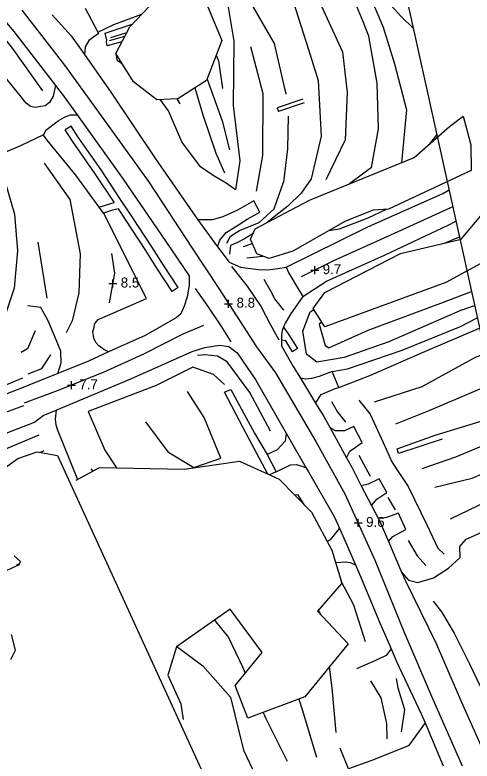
# Model space of a CAD drawing. Extents: x 2316231 to 2323598, y 363169 to 371906.
# Drawn here: x 2320809.7 to 2321039.3, y 364491.7 to 364866.8 of the extents above; entities that cross this region are included whole.
import ezdxf

# ---------------------------------------------------------------- set-up
doc = ezdxf.new("R2010")
doc.units = 0
for name, color, linetype in [('RD_DTM_BkLn1', 7, 'Continuous'), ('RD_DTM_BkLn2', 7, 'Continuous'), ('RD_DTM_Holes', 7, 'Continuous'), ('RD_DTM_TinHull', 7, 'Continuous'), ('RD_DTM_Void', 7, 'Continuous'), ('RD_EX_Road', 7, 'Continuous')]:
    doc.layers.add(name, color=color, linetype=linetype)

msp = doc.modelspace()

# ---------------------------------------------------------------- linework, layer by layer
at = {"layer": 'RD_DTM_BkLn1'}
for p, q in [((2320857.922, 364855.442), (2320865.884, 364857.984)), ((2320857.161, 364854.013), (2320864.941, 364856.17)), ((2320890.993, 364824.643), (2320892.539, 364822.049)), ((2321021.612, 364806.726), (2321017.953, 364801.935)), ((2320988.788, 364790.183), (2320977.746, 364781.912)), ((2320825.894, 364724.379), (2320821.285, 364752.599)), ((2321025.529, 364752.138), (2321033.007, 364755.165)), ((2320924.511, 364750.44), (2320928.932, 364751.87)), ((2320926.195, 364744.639), (2320934.141, 364745.607)), ((2321034.418, 364718.599), (2321040.607, 364720.781)), ((2321020.775, 364655.454), (2321052.876, 364665.268)), ((2320821.672, 364655.549), (2320782.321, 364639.059)), ((2320822.25, 364646.821), (2320824.303, 364647.793)), ((2320982.482, 364645.549), (2320988.198, 364634.922)), ((2320847.881, 364638.589), (2320848.738, 364637.393)), ((2320997.044, 364624.211), (2321000.661, 364617.915)), ((2320962.235, 364567.615), (2320963.132, 364565.607))]:
    msp.add_line(p, q, dxfattribs=at)
for points in [[(2320908.522, 364997.717), (2320917.208, 364986.663), (2320929.547, 364969.312), (2320941.727, 364952.475), (2320951.651, 364938.282), (2320962.989, 364924.745), (2320974.367, 364912.172), (2320983.382, 364900.815), (2320991.979, 364890.119), (2320998.704, 364879.261), (2320998.587, 364871.774), (2321003.76, 364866.025), (2321009.84, 364859.987)], [(2320789.301, 364937.875), (2320795.11, 364943.095), (2320806.689, 364952.583), (2320818.553, 364960.506), (2320831.082, 364969.075), (2320846.132, 364977.365), (2320860.519, 364984.44), (2320870.598, 364987.867), (2320889.653, 364988.831), (2320900.365, 364987.807), (2320908.475, 364980.988), (2320916.282, 364973.127), (2320926.017, 364960.544), (2320937.809, 364940.963), (2320942.748, 364927.859), (2320950.518, 364916.033), (2320963.998, 364909.262), (2320972.13, 364900.847), (2320985.96, 364881.366), (2320994.687, 364860.701), (2321000.435, 364842.191), (2321006.362, 364819.106), (2321003.87, 364792.554)], [(2320810.535, 364940.389), (2320825.111, 364948.104), (2320854.856, 364964.167), (2320876.979, 364971.002), (2320892.242, 364970.12), (2320908.18, 364962.846), (2320915.576, 364953.824), (2320929.031, 364935.515), (2320932.634, 364927.541), (2320935.334, 364914.389), (2320942.929, 364902.839), (2320955.2, 364890.276), (2320964.566, 364869.376), (2320974.238, 364848.22), (2320976.597, 364827.739), (2320975.536, 364803.965), (2320965.865, 364783.98)], [(2320842.068, 364950.483), (2320865.195, 364952.17), (2320885.293, 364946.76), (2320899.752, 364933.281), (2320911.245, 364920.421), (2320921.248, 364895.307), (2320929.317, 364870.652), (2320939.891, 364852.388), (2320945.723, 364827.042)], [(2320810.699, 364934.838), (2320827.79, 364939.679), (2320849.336, 364941.617), (2320871.046, 364940.278), (2320885.78, 364932.975), (2320899.408, 364919.593), (2320903.204, 364911.842), (2320908.706, 364897.372), (2320916.477, 364872.722), (2320919.668, 364853.585), (2320919.271, 364821.299), (2320922.598, 364793.419), (2320920.431, 364778.915), (2320915.816, 364782.273), (2320909.315, 364786.101), (2320902.858, 364790.501), (2320893.539, 364802.97), (2320886.757, 364818.567), (2320882.826, 364824.202)], [(2320988.788, 364790.183), (2320992.4, 364809.56), (2320991.664, 364832.54), (2320987.459, 364856.087), (2320984.732, 364862.94), (2320979.791, 364875.211), (2320973.159, 364886.674), (2320968.431, 364894.237), (2320960.28, 364902.211), (2320953.763, 364908.088)], [(2320776.661, 364884.847), (2320788.473, 364874.922), (2320808.365, 364850.154), (2320823.472, 364828.593)], [(2320941.949, 364883.529), (2320949.496, 364873.493), (2320957.099, 364849.476), (2320961.964, 364833.885), (2320963.6, 364805.937), (2320958.573, 364784.428), (2320953.495, 364777.255), (2320946.856, 364770.739), (2320940.697, 364765.929), (2320936.198, 364762.314)], [(2320813.139, 364869.191), (2320834.594, 364841.589), (2320851.668, 364817.936), (2320876.795, 364782.989), (2320898.779, 364749.615), (2320912.035, 364729.273), (2320922.885, 364712.636), (2320930.999, 364700.019), (2320940.535, 364686.939), (2320960.87, 364652.4), (2320975.496, 364625.988), (2320990.714, 364592.422), (2321005.138, 364556.892), (2321019.52, 364523.148), (2321034.445, 364489.194)], [(2320931.017, 364778.19), (2320934.191, 364796.18), (2320934.318, 364827.196), (2320928.233, 364850.784)], [(2320863.597, 364842.267), (2320861.179, 364843.674), (2320860.575, 364847.214)], [(2320910.841, 364846.594), (2320912.012, 364843.738), (2320913.974, 364829.788)], [(2320906.209, 364834.493), (2320913.805, 364813.62), (2320917.411, 364799.049)], [(2320900.135, 364830.126), (2320904.026, 364816.524), (2320910.633, 364797.345), (2320915.015, 364787.429)], [(2320946.966, 364815.913), (2320946.685, 364799.414), (2320944.555, 364782.729)], [(2320824.405, 364792.273), (2320837.253, 364773.974), (2320842.399, 364746.638), (2320841.726, 364727.144), (2320838.397, 364713.014), (2320835.41, 364707.024)], [(2320804.969, 364782.158), (2320809.477, 364766.572), (2320810.929, 364748.236), (2320809.327, 364729.495), (2320804.968, 364716.442)], [(2320916.177, 364752.035), (2320918.054, 364755.578), (2320922.54, 364758.389), (2320932.344, 364762.499), (2320939.963, 364769.286), (2320944.555, 364782.729)], [(2321029.649, 364770.36), (2321028.562, 364769.832), (2320998.376, 364756.039), (2320969.418, 364743.083), (2320953.527, 364735.056)], [(2320967.442, 364758.383), (2320972.671, 364759.298), (2320987.129, 364764.799), (2320996.273, 364769.142)], [(2320929.338, 364756.954), (2320924.927, 364754.161), (2320921.553, 364752.368), (2320917.909, 364750.865), (2320917.401, 364746.538)], [(2320858.168, 364746.844), (2320859.763, 364736.924), (2320857.077, 364722.011)], [(2320918.448, 364740.354), (2320926.378, 364730.455), (2320933.383, 364719.986), (2320937.916, 364711.366), (2320942.307, 364703.534)], [(2320944.73, 364718.404), (2320940.305, 364724.022), (2320938.162, 364727.865), (2320934.943, 364733.75)], [(2320900.307, 364729.302), (2320906.595, 364720.214), (2320913.076, 364710.503), (2320918.189, 364702.434)], [(2320963.869, 364712.319), (2320962.491, 364711.256), (2320965.515, 364700.528), (2320967.366, 364699.38), (2320987.153, 364708.335), (2321023.587, 364721.971), (2321039.079, 364727.692)], [(2321034.418, 364718.599), (2320997.539, 364702.41), (2320975.149, 364694.543), (2320961.373, 364692.27), (2320956.232, 364696.255), (2320954.387, 364707.739), (2320957.933, 364717.495), (2320959.882, 364718.675)], [(2320904.423, 364710.71), (2320894.102, 364706.322), (2320873.866, 364696.029), (2320854.031, 364687.027), (2320830.834, 364677.768), (2320814.306, 364671.594)], [(2320819.876, 364708.052), (2320815.948, 364698.981), (2320812.768, 364697.043)], [(2320816.327, 364686.282), (2320823.14, 364689.081), (2320827.664, 364695.905)], [(2320938.122, 364657.459), (2320927.699, 364676.97), (2320916.269, 364692.319), (2320911.385, 364695.205), (2320905.037, 364695.876), (2320901.375, 364695.504)], [(2320990.259, 364672.362), (2321014.229, 364680.025), (2321041.059, 364694.717), (2321045.94, 364696.648)], [(2320914.937, 364680.992), (2320909.408, 364686.067), (2320898.975, 364689.695), (2320880.565, 364680.504), (2320846.533, 364667.426)], [(2320813.41, 364684.179), (2320805.414, 364680.785), (2320801.821, 364679.874), (2320798.958, 364679.173), (2320796.598, 364678.011), (2320792.846, 364676.308), (2320784.749, 364672.755)], [(2321000.981, 364661.288), (2321017.755, 364667.968), (2321049.323, 364681.342)], [(2320875.266, 364662.179), (2320886.462, 364647.072), (2320899.545, 364639.283), (2320913.06, 364643.883), (2320904.689, 364664.446), (2320896.331, 364677.496)], [(2320982.52, 364673.174), (2320988.09, 364666.157), (2320994.714, 364651.896), (2320999.151, 364641.717), (2321007.276, 364629.755), (2321016.756, 364610.067), (2321022.174, 364598.635), (2321025.367, 364595.667)], [(2320761.146, 364648.891), (2320785.759, 364659.479), (2320805.172, 364667.165), (2320814.1, 364670.455)], [(2320968.792, 364672.459), (2320971.631, 364667.461), (2320975.773, 364662.027)], [(2320846.533, 364667.426), (2320854.791, 364648.019), (2320860.746, 364639.052)], [(2321014.287, 364638.778), (2321031.215, 364644.622), (2321055.222, 364654.654)], [(2321020.583, 364629.392), (2321039.348, 364633.933), (2321058.029, 364641.952)], [(2320950.129, 364625.49), (2320951.583, 364625.742), (2320954.793, 364620.717)], [(2321028.55, 364613.491), (2321047.002, 364622.383), (2321061.146, 364627.85)], [(2321007.232, 364602.535), (2321011.839, 364594.855), (2321016.049, 364589.955)], [(2320810.975, 364589.985), (2320810.794, 364590.419), (2320812.056, 364590.993)], [(2320973.443, 364582.365), (2320979.842, 364570.277), (2320985.637, 364551.755)], [(2321019.82, 364572.13), (2321023.963, 364566.779), (2321030.308, 364555.987), (2321038.093, 364540.576), (2321049.079, 364517.388), (2321059.888, 364492.083)], [(2320909.879, 364562.492), (2320916.976, 364553.731), (2320923.95, 364539.036), (2320925.409, 364535.836)], [(2320891.035, 364549.213), (2320904.038, 364539.597), (2320917.997, 364523.792), (2320924.509, 364497.066), (2320931.829, 364481.592)], [(2320967.573, 364539.046), (2320968.95, 364528.522), (2320970.956, 364506.022)], [(2320988.39, 364532.029), (2320993.458, 364523.389), (2320996.33, 364510.532), (2320996.484, 364502.885)], [(2321001.28, 364533.233), (2321002.05, 364528.41), (2321005.381, 364517.535), (2321003.705, 364506.285)], [(2320952.287, 364522.819), (2320954.039, 364517.633), (2320961.129, 364493.542)], [(2320934.422, 364516.063), (2320935.785, 364513.072), (2320946.394, 364491.688)]]:
    msp.add_lwpolyline(points, dxfattribs=at)
at = {"layer": 'RD_DTM_BkLn2'}
for points in [[(2320813.835, 364679.431), (2320798.583, 364673.706), (2320785.827, 364668.854), (2320775.48, 364664.655), (2320768.989, 364662.198), (2320754.788, 364656.259), (2320754.267, 364655.838), (2320754.259, 364655.36)], [(2320776.858, 364644.163), (2320782.736, 364647.15), (2320793.891, 364652.025), (2320806.074, 364656.853), (2320819.585, 364662.004)]]:
    msp.add_lwpolyline(points, dxfattribs=at)
at = {"layer": 'RD_DTM_Holes'}
for points in [[(2320860.417, 364847.473), (2320867.353, 364860.808), (2320880.49, 364874.76), (2320895.367, 364877.398), (2320906.613, 364870.852), (2320913.685, 364854.024), (2320905.951, 364833.819), (2320891.544, 364824.673), (2320880.937, 364824.1), (2320869.171, 364833.142), (2320860.417, 364847.473)], [(2321034.819, 364815.97), (2321038.641, 364801.467), (2321038.928, 364788.615), (2320997.295, 364769.213), (2320989.643, 364768.678), (2320975.695, 364763.049), (2320949.218, 364748.078), (2320937.431, 364744.392), (2320931.133, 364746.717), (2320928.02, 364754.005), (2320930.34, 364759.196), (2320957.595, 364773.703), (2321010.179, 364795.124), (2321027.925, 364810.672), (2321034.819, 364815.97)], [(2321043.787, 364765.784), (2321045.794, 364751.691), (2321043.724, 364741.876), (2321026.13, 364732.303), (2320965.317, 364710.009), (2320959.555, 364719.196), (2320965.397, 364727.297), (2321003.341, 364746.852), (2321033.829, 364754.116), (2321043.787, 364765.784)], [(2320791.882, 364630.089), (2320811.181, 364643.862), (2320820.79, 364647.063), (2320831.038, 364645.366), (2320909.676, 364473.622)], [(2320840.465, 364632.876), (2320852.094, 364639.226), (2320894.708, 364638.37), (2320922.515, 364642.378), (2320942.367, 364633.435), (2320958.623, 364616.797), (2320968.805, 364597.777), (2320973.842, 364581.04), (2320961.764, 364567.071), (2320977.071, 364550.686), (2320955.245, 364523.937), (2320926.761, 364513.165), (2320920.338, 364529.614), (2320933.898, 364546.251), (2320917.807, 364568.078), (2320890.778, 364549.032), (2320886.556, 364534.904), (2320893.105, 364520.406), (2320894.155, 364512.555)], [(2320802.932, 364586.35), (2320810.468, 364589.756), (2320811.853, 364590.382), (2320812.411, 364592.061), (2320809.356, 364594.862)], [(2320807.609, 364542.745), (2320809.884, 364547.472), (2320807.907, 364555.292)]]:
    msp.add_lwpolyline(points, dxfattribs=at)
at = {"layer": 'RD_DTM_TinHull'}
msp.add_lwpolyline([(2320809.363, 365353.877), (2320991.706, 364942.038), (2321080.196, 364541.654), (2321314.653, 364017.924), (2320828.919, 363723.372), (2320765.1, 363867.546), (2320638.089, 364094.01), (2320532.322, 364258.493), (2320402.792, 364459.125), (2320263.728, 364603.235), (2320177.718, 364755.167), (2319998.644, 364909.111), (2319975.332, 365147.552), (2319890.016, 365354.444)], dxfattribs=at)
at = {"layer": 'RD_DTM_Void'}
for p, q in [((2320958.3, 364738.477), (2320962.3, 364738.477)), ((2320960.3, 364736.477), (2320960.3, 364740.477)), ((2320858.834, 364729.764), (2320858.834, 364733.764)), ((2320856.834, 364731.764), (2320860.834, 364731.764)), ((2320917.02, 364719.63), (2320917.02, 364723.63)), ((2320915.02, 364721.63), (2320919.02, 364721.63)), ((2320836.03, 364680.64), (2320840.03, 364680.64)), ((2320838.03, 364678.64), (2320838.03, 364682.64)), ((2320982.114, 364609.39), (2320982.114, 364613.39)), ((2320980.114, 364611.39), (2320984.114, 364611.39))]:
    msp.add_line(p, q, dxfattribs=at)
at = {"layer": 'RD_EX_Road'}
for p, q in [((2320845.019, 364870.149), (2320851.364, 364858.212)), ((2320830.127, 364831.326), (2320832.3, 364828.51)), ((2320954.342, 364824.406), (2320941.474, 364820.046)), ((2320941.474, 364820.046), (2320942.081, 364818.252)), ((2320954.95, 364822.612), (2320942.081, 364818.252)), ((2320837.948, 364810.904), (2320834.943, 364808.964)), ((2320854.239, 364767.074), (2320852.033, 364770.099)), ((2320901.513, 364763.876), (2320911.477, 364750.268)), ((2320891.659, 364729.693), (2320888.671, 364727.727)), ((2320972.379, 364679.559), (2320969.028, 364687.59)), ((2320953.082, 364684.116), (2320960.744, 364671.653)), ((2320968.037, 364659.164), (2320976.267, 364644.152)), ((2320946.018, 364656.484), (2320955.902, 364639.311)), ((2320936.38, 364645.769), (2320940.852, 364637.066)), ((2320940.852, 364637.066), (2320937.557, 364635.602)), ((2320983.678, 364630.11), (2320988.848, 364620.091)), ((2320988.848, 364620.091), (2320992.106, 364613.776)), ((2320972.674, 364608.72), (2320980.76, 364590.26)), ((2320997.326, 364602.026), (2321003.903, 364586.719)), ((2321015.798, 364510.839), (2321024.89, 364489.308))]:
    msp.add_line(p, q, dxfattribs=at)
for points in [[(2320830.127, 364831.326), (2320828.955, 364825.935), (2320826.977, 364822.775), (2320824.855, 364821.093), (2320822.706, 364820.71), (2320820.21, 364820.261), (2320817.564, 364820.826), (2320815.279, 364822.469), (2320812.068, 364826.508), (2320797.38, 364844.432), (2320771.545, 364875.949), (2320769.061, 364876.249), (2320765.48, 364877.96), (2320763.665, 364879.93), (2320762.196, 364882.667), (2320762.258, 364885.893), (2320764.822, 364889.164), (2320769.089, 364891.002), (2320775.022, 364892.731), (2320777.755, 364893.117), (2320780.488, 364892.295)], [(2320780.488, 364892.295), (2320781.839, 364890.827), (2320809.138, 364858.525), (2320830.127, 364831.326)], [(2320828.446, 364866.907), (2320837.849, 364856.386), (2320844.587, 364846.845)], [(2320851.364, 364858.212), (2320859.321, 364861.945), (2320873.393, 364867.223)], [(2320863.458, 364853.319), (2320855.951, 364851.222), (2320855.616, 364853.43), (2320855.914, 364854.187), (2320855.038, 364857.582), (2320868.61, 364862.142)], [(2320851.364, 364858.212), (2320851.715, 364857.551), (2320846.73, 364853.985), (2320844.966, 364850.845), (2320844.587, 364846.845)], [(2320844.587, 364846.845), (2320857.898, 364827.996), (2320880.008, 364795.049), (2320900.36, 364765.451), (2320901.513, 364763.876)], [(2320832.3, 364828.51), (2320833.636, 364826.779), (2320840.874, 364816.632)], [(2320824.14, 364806.552), (2320825.116, 364808.837), (2320831.477, 364813.584), (2320834.89, 364815.543), (2320837.514, 364816.645), (2320840.874, 364816.632)], [(2320840.874, 364816.632), (2320863.967, 364784.261), (2320885.411, 364752.92), (2320897.166, 364735.566), (2320897.131, 364731.018), (2320896.288, 364725.078), (2320894.726, 364720.327), (2320892.976, 364716.544), (2320890.633, 364714.45), (2320875.088, 364705.702), (2320856.744, 364697.372)], [(2320852.033, 364770.099), (2320857.774, 364772.067), (2320859.551, 364772.491), (2320859.477, 364772.602), (2320849.993, 364786.881), (2320838.516, 364803.43), (2320834.943, 364808.964)], [(2320891.659, 364729.693), (2320884.236, 364740.975), (2320878.395, 364750.254), (2320868.243, 364765.875), (2320862.456, 364774.581), (2320852.953, 364788.89), (2320841.489, 364805.42), (2320837.948, 364810.904)], [(2320824.044, 364806.52), (2320812.54, 364801.043), (2320800.842, 364796.154), (2320784.183, 364785.435)], [(2320852.033, 364770.099), (2320840.232, 364786.287), (2320825.824, 364803.849), (2320824.09, 364806.436), (2320824.14, 364806.552)], [(2320945.959, 364739.913), (2320959.185, 364746.589), (2320986.591, 364760.069), (2321024.734, 364777.108), (2321027.781, 364778.81)], [(2320911.477, 364750.268), (2320912.664, 364753.542), (2320915.856, 364757.386), (2320922.036, 364761.207), (2320926.32, 364764.093), (2320932.674, 364767.614), (2320929.643, 364773.341), (2320921.485, 364768.646), (2320914.194, 364765.354), (2320908.694, 364763.857), (2320901.513, 364763.876)], [(2320856.744, 364697.372), (2320854.367, 364698.679), (2320851.883, 364700.504), (2320850.396, 364702.087), (2320849.288, 364704.355), (2320848.78, 364707.661), (2320849.257, 364709.237), (2320849.879, 364711.704), (2320851.566, 364713.726), (2320856.158, 364715.726), (2320875.7, 364724.304), (2320862.202, 364751.294), (2320854.466, 364766.763), (2320854.239, 364767.074)], [(2320888.671, 364727.727), (2320881.229, 364739.039), (2320875.382, 364748.327), (2320865.254, 364763.91), (2320861.66, 364769.317), (2320858.771, 364768.628), (2320854.239, 364767.074)], [(2320954.385, 364725.183), (2320966.129, 364733.025), (2320995.422, 364746.083), (2321027.27, 364761.065), (2321031.261, 364763.065)], [(2320911.477, 364750.268), (2320912.566, 364748.781), (2320917.308, 364742.497)], [(2320917.308, 364742.497), (2320922.955, 364739.986), (2320933.163, 364738.672), (2320938.154, 364738.808), (2320941.771, 364739.395), (2320945.959, 364739.913)], [(2320945.959, 364739.913), (2320947.271, 364737.035), (2320951.507, 364729.955), (2320954.385, 364725.183)], [(2320954.385, 364725.183), (2320948.198, 364716.325), (2320945.436, 364711.784), (2320944.632, 364709.812)], [(2320831.261, 364686.537), (2320832.982, 364691.833), (2320832.717, 364697.731), (2320830.389, 364703.423), (2320826.324, 364713.048), (2320822.629, 364719.691), (2320815.975, 364720.568)], [(2320969.028, 364687.59), (2320976.704, 364688.887), (2321004.155, 364698.329), (2321033.596, 364710.17), (2321041.984, 364714.549)], [(2320944.632, 364709.812), (2320947.214, 364705.898), (2320951.644, 364699.113), (2320949.153, 364697.39), (2320945.704, 364703.016), (2320943.672, 364703.23)], [(2320944.632, 364709.812), (2320943.975, 364708.199), (2320943.68, 364706.049), (2320943.672, 364703.23)], [(2320972.379, 364679.559), (2320987.927, 364685.461), (2321017.132, 364698.198), (2321043.125, 364709.385)], [(2320943.672, 364703.23), (2320943.664, 364700.464), (2320949.396, 364690.111), (2320953.082, 364684.116)], [(2320830.392, 364668.158), (2320867.973, 364683.892), (2320898.656, 364697.523), (2320905.024, 364699.65), (2320912.507, 364700.724), (2320917.165, 364700.104), (2320921.293, 364696.86), (2320930.677, 364683.175), (2320943.463, 364660.924), (2320946.018, 364656.484)], [(2320856.744, 364697.372), (2320846.619, 364692.775), (2320831.261, 364686.537)], [(2320831.261, 364686.537), (2320816.637, 364680.597), (2320813.84, 364679.529)], [(2320969.028, 364687.59), (2320962.474, 364684.989), (2320958.637, 364684.072), (2320955.654, 364683.643), (2320953.082, 364684.116)], [(2320936.81, 364635.938), (2320924.372, 364659.162), (2320914.936, 364677.074), (2320918.125, 364678.489), (2320930.035, 364656.549), (2320936.38, 364645.769)], [(2320960.744, 364671.653), (2320963.535, 364675.911), (2320970.538, 364679.052), (2320972.379, 364679.559)], [(2320960.744, 364671.653), (2320964.852, 364664.971), (2320968.037, 364659.164)], [(2320819.585, 364662.004), (2320823.83, 364665.41), (2320830.392, 364668.158)], [(2320830.392, 364668.158), (2320829.957, 364663.576), (2320830.295, 364660.785), (2320830.856, 364658.561), (2320841.027, 364633.183)], [(2320976.267, 364644.152), (2320977.867, 364647.42), (2320984.129, 364651.918), (2320980.001, 364659.805), (2320975.218, 364657.725), (2320970.753, 364657.783), (2320968.037, 364659.164)], [(2320946.018, 364656.484), (2320945.465, 364652.581), (2320941.502, 364648.142), (2320936.38, 364645.769)], [(2321024.401, 364653.54), (2321002.461, 364646.274), (2321001.702, 364648.726), (2321020.775, 364655.454)], [(2320976.267, 364644.152), (2320979.081, 364639.018), (2320983.678, 364630.11)], [(2320940.852, 364637.066), (2320948.089, 364640.669), (2320951.198, 364640.751), (2320955.902, 364639.311)], [(2320955.902, 364639.311), (2320957.224, 364637.013), (2320970.08, 364614.641), (2320972.674, 364608.72)], [(2320988.848, 364620.091), (2320991.494, 364623.357), (2320996.465, 364626.756), (2320992.75, 364633.601), (2320987.207, 364630.925), (2320983.678, 364630.11)], [(2320997.326, 364602.026), (2320999.549, 364604.62), (2321005.985, 364608.092), (2321002.433, 364616.268), (2320996.303, 364614.089), (2320993.569, 364613.608), (2320992.106, 364613.776)], [(2320992.106, 364613.776), (2320993.124, 364611.805), (2320997.326, 364602.026)], [(2321003.903, 364586.719), (2321007.481, 364582.622), (2321012.083, 364581.467), (2321019.895, 364583.822), (2321027.423, 364588.574), (2321033.378, 364593.983), (2321033.262, 364599.509), (2321036.38, 364603.247), (2321040.494, 364605.136), (2321063.823, 364615.735)], [(2320972.674, 364608.72), (2320968.05, 364602.825), (2320966.481, 364602.118)], [(2320970.708, 364591.452), (2320975.904, 364591.855), (2320978.114, 364591.547), (2320980.76, 364590.26)], [(2320980.76, 364590.26), (2320983.325, 364584.405), (2320993.059, 364561.117), (2320998.627, 364548.157)], [(2321003.903, 364586.719), (2321005.682, 364582.579), (2321021.297, 364550.841), (2321034.078, 364521.338), (2321049.466, 364486.704)], [(2320998.627, 364548.157), (2320996.243, 364544.671), (2320992.407, 364542.98), (2320981.315, 364537.998)], [(2320998.627, 364548.157), (2321001.412, 364541.673), (2321013.851, 364515.45), (2321015.798, 364510.839)], [(2321015.798, 364510.839), (2321007.347, 364499.262), (2320988.404, 364491.758), (2320977.21, 364487.837), (2320973.025, 364498.178)]]:
    msp.add_lwpolyline(points, dxfattribs=at)

# ---------------------------------------------------------------- texts
at = {"layer": 'RD_DTM_Void'}
for s, p in [('9.7', (2320964.3, 364736.477)), ('8.5', (2320862.834, 364729.764)), ('8.8', (2320921.02, 364719.63)), ('7.7', (2320842.03, 364678.64)), ('9.6', (2320986.114, 364609.39))]:
    msp.add_text(s, height=5, dxfattribs=at).set_placement(p)

doc.saveas('drawing.dxf')
